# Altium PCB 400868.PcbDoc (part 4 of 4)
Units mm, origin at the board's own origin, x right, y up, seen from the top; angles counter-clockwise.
Board outline 117 x 63.5 mm, 4 copper layers (Top Layer, Mid-Layer 1, Mid-Layer 2, Bottom Layer), stack 1.58 mm thick; 211 components, 153 nets, 878 pads, 1351 vias.
Unrouted connection lines stored in the file: 16.
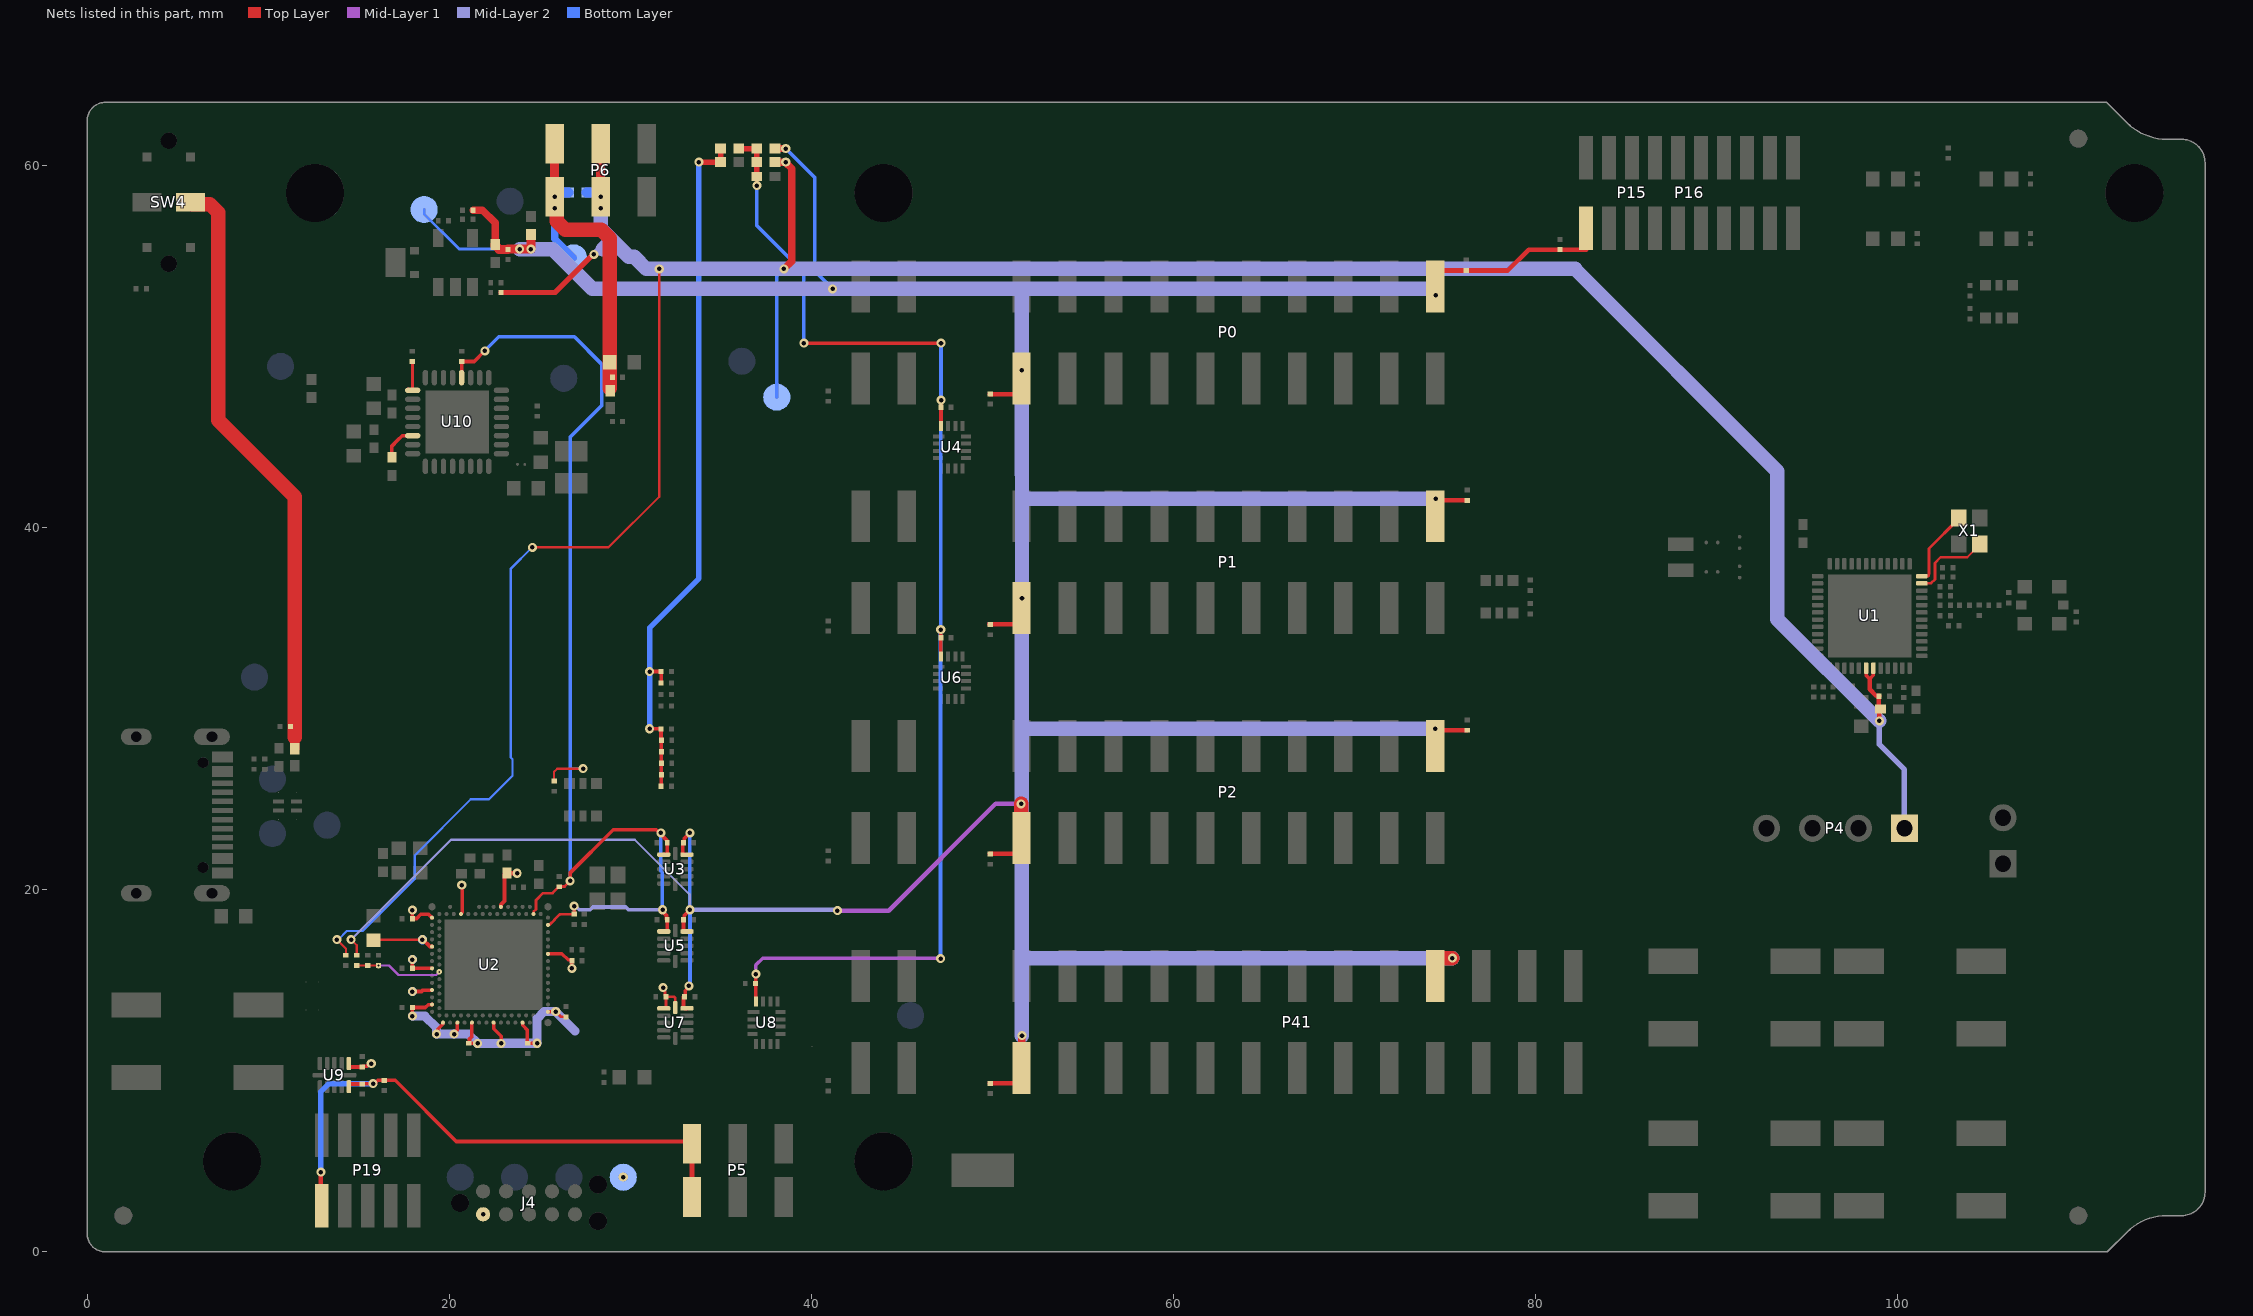
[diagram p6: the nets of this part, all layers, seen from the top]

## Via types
v1: diameter 0.5, hole 0.25, Top Layer to Bottom Layer, tented both sides, 1252 vias
v2: diameter 0.3, hole 0.1, Top Layer to Mid-Layer 1, tented top, 72 vias
v3: diameter 0.3, hole 0.1, Top Layer to Mid-Layer 1, tented both sides, 18 vias
v4: diameter 0.5, hole 0.25, Top Layer to Bottom Layer, tented bottom, 9 vias

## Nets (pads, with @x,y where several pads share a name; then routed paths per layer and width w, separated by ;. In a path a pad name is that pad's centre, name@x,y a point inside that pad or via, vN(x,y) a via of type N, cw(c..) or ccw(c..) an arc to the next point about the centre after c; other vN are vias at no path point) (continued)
VBUS:IN2: C46.2 FB3.2 SW4.5 | length 33.1
  Top Layer w0.5: FB3.2@11.475,27.8 11.475,28.423
  Top Layer w0.8: SW4.5@5.721,57.988 5.821,57.888 6.781,57.888 7.25,57.42 7.25,45.95 11.475,41.725 11.475,29.025 11.475,28.423
VBUS:OUT: C76.2 U10.22 | length 2
  Top Layer w0.2: C76.2@16.842,43.896 16.842,44.519 17.169,44.846 17.409,45.086 17.981,45.086 U10.22@17.992,45.096
VDD:DBGR: C15.2 C17.1 C18.1 C20.1 C22.1 C29.1 C31.1 C34.1 C35.1 C36.1 C37.1 C40.1 C53.2 C66.2 C68.2 J4.1 R6.2 R8.2 TP3.1 U2.A19 U2.AC1 U2.AG1 U2.AJ31 U2.AL3 U2.AL7 U2.AL11 U2.AL17 U2.AL25 U2.B8 U2.B28 U2.C1 U2.E31 U2.L1 U2.N31 U2.U1 U3.1 U5.1 U7.1 U7.12 U9.1 U10.12 | length 105.6
  Top Layer w0.125: C40.1@15.825,17.225 15.85,17.25 v1(18.525,17.25) ; R8.2@25.8,26.019 25.8,26.519 25.975,26.694 v1(27.4,26.694)
  Top Layer w0.15: U9.1@14.464,10.405 14.464,10.35 U9.1@14.514,10.3 ; U2.B28@24.66,18.664 24.675,18.679 24.675,18.801 24.798,18.925 24.798,19.204 24.798,19.428 25.185,19.815 25.722,19.815 26.081,20.174 C37.1@26.096,20.174 26.11,20.188 26.383,20.188 v1(26.685,20.49) ; U2.E31@25.443,18.079 25.562,18.079 25.824,18.341 25.824,18.364 26.102,18.642 26.125,18.642 26.134,18.651 26.899,18.651 C36.1@26.909,18.661 ; v1(25.893,13.271) 26.173,12.991 26.455,12.991 R6.2@26.46,12.986 ; v1(31.825,14.6) 31.825,14.505 31.929,14.402 31.929,14.16 31.946,14.143 C68.2@31.989,14.143 ; U7.1@31.86,13.45 31.939,13.45 31.989,13.5 C68.2@31.989,14.143 ; U7.12@32.5,13.5 32.5,14.012 32.412,14.1 32.031,14.1 C68.2@31.989,14.143
  Top Layer w0.187: U2.B8@20.66,18.664 20.66,18.675 20.735,18.75 v1@20.735,20.265 ; U2.N31@25.46,16.464 26.236,16.464 26.572,16.128 C35.1@26.692,16.128
  Top Layer w0.2: U9.1@14.489,10.625 14.464,10.6 U9.1@14.464,10.405 14.464,10.24 14.489,10.215 C53.2@15.2,10.215 15.235,10.25 15.469,10.25 15.619,10.4 v1(15.7,10.4) ; v1(17.968,13.03) 17.968,13.471 17.981,13.471 18.009,13.499 18.682,13.499 18.842,13.66 19.056,13.66 U2.AG1@19.06,13.664 ; v1(17.968,14.381) 17.976,14.388 18.482,14.388 18.558,14.464 U2.AC1@19.06,14.464 ; v1(17.968,18.884) 17.971,18.881 17.971,18.404 C17.1@17.974,18.401 17.992,18.42 18.209,18.42 18.439,18.65 18.865,18.65 19.046,18.469 19.049,18.469 19.056,18.462 19.056,18.46 U2.C1@19.06,18.464 ; C18.1@17.974,15.63 v1@17.974,16.149 ; C18.1@17.979,15.664 U2.U1@19.06,15.664 ; v1(18.525,17.25) 18.562,17.25 18.943,16.869 19.056,16.869 U2.L1@19.06,16.864 ; v1(19.314,12.026) 19.372,12.083 19.372,12.296 19.656,12.58 19.656,12.66 U2.AL3@19.66,12.664 ; v1(20.28,12.026) 20.28,12.107 20.46,12.288 U2.AL7@20.46,12.664 ; U10.12@20.7,48.304 20.7,49.19 21.39,49.19 v1(21.975,49.775) ; C22.1@21.092,11.524 21.127,11.559 21.13,11.559 21.13,11.759 21.26,11.889 U2.AL11@21.26,12.664 ; C22.1@21.101,11.521 21.572,11.521 v1(21.575,11.518) ; U2.AL17@22.46,12.664 22.46,12.334 22.878,11.916 v1(22.878,11.518) ; U2.AL25@24.06,12.664 24.065,12.66 24.065,12.514 24.318,12.261 24.318,11.549 C34.1@24.344,11.524 24.346,11.521 24.856,11.521 v1(24.86,11.525) ; U2.AJ31@25.46,13.264 25.887,13.264 v1(25.893,13.271) ; v1(26.685,20.49) 26.685,20.935 29.075,23.325 31.444,23.325 31.619,23.15 v1(31.7,23.15) 31.7,23.069 32.016,22.753 32.016,22.639 C15.2@32.051,22.604 32.051,21.975 32.026,21.95 U3.1@31.86,21.95 ; C35.1@26.692,16.128 26.748,16.128 26.783,16.093 C35.1@26.783,16.078 v1(26.782,15.659) ; v1@31.696,18.9 32.013,18.583 C66.2@32.013,18.389 ; U5.1@31.856,17.7 32.023,17.7 32.048,17.725 C66.2@32.048,18.354
  Top Layer w0.203: v1(26.908,19.101) 26.909,19.1 C36.1@26.909,18.661
  Top Layer w0.225: U2.A19@22.86,19.064 22.86,19.179 23.074,19.392 23.074,20.848 C31.1@23.15,20.924 ; C31.1@23.201,20.916 v1(23.759,20.916)
  Mid-Layer 1 w0.2: v1@21.541,11.484 v1(21.575,11.518) v1@21.632,11.461
  Mid-Layer 2 w0.2: v1(26.908,19.101) 26.989,19.101 27.19,18.9 27.803,18.9 27.953,19.05 29.761,19.05 29.911,18.9 v1(31.8,18.9)
  Mid-Layer 2 w0.5: v1(17.968,13.03) 18.666,13.03 19.295,12.401 19.295,12.045 v1(19.314,12.026) v1(20.28,12.026) 21.067,12.026 v1(21.575,11.518) v1(22.878,11.518) 22.885,11.525 v1(24.86,11.525) 24.86,12.889 25.242,13.271 v1(25.893,13.271) 26.964,12.2
  Bottom Layer w0.125: 26.685,26.694 v1(27.4,26.694)
  Bottom Layer w0.2: v1(21.575,11.518) v1@21.656,11.518 ; v1(21.878,2.074) v1@21.914,2.11 ; v1(21.975,49.775) 22.75,50.55 26.925,50.55 28.425,49.05 28.425,46.739 26.685,44.999 26.685,26.694 v1(26.685,20.49) ; v1(31.7,23.15) 31.7,21.046 31.775,20.971 31.775,18.925 v1(31.8,18.9)
  Bottom Layer w0.4: v1@17.968,18.911 v1(17.968,18.884) v1@17.987,18.865
  Bottom Layer w0.5: v1(17.968,14.381) v1@17.975,14.388 ; v1@18.534,17.242 v1(18.525,17.25) v1@18.534,17.258
  other v1: 29.621,4.125 17.975,16.15 20.7,20.266
VDD:IO: C16.1 C51.2 C52.2 C61.2 C62.2 C64.2 C65.2 C67.1 C69.1 C72.2 C79.2 C80.1 C81.2 P0.1 P0.20 P1.1 P1.20 P2.1 P2.20 P15.1 P16.1 P41.1 P41.20 R25.2 R46.2 R50.1 R54.2 TP11.1 U3.11 U5.11 U7.11 | length 271.4
  Top Layer w0.125: v1(14.589,17.251) 14.9,16.94 R46.2@14.9,16.385 ; U3.11@33.145,21.955 32.942,21.955 32.94,21.955 32.877,22.017 32.877,22.032 32.917,22.024 32.955,22.017 33.146,21.979 U3.11@33.149,21.979
  Top Layer w0.2: U3.11@32.942,21.955 32.917,21.98 32.917,22.024 32.917,22.558 32.918,22.574 32.988,22.644 32.988,22.838 v1(33.3,23.15) ; C69.1@32.952,14.104 32.952,13.475 32.977,13.45 U7.11@33.14,13.45 U7.11@33.144,13.45 ; C67.1@32.952,18.354 32.952,17.725 32.977,17.7 U5.11@33.14,17.7 U5.11@33.144,17.7 ; C69.1@32.987,14.135 33.05,14.135 33.05,14.419 33.25,14.619 v1(33.25,14.7) ; C67.1@32.987,18.389 32.987,18.583 v1@33.304,18.9
  Top Layer w0.25: U7.11@33.032,13.45 U7.11@33.14,13.45 ; C61.2@49.834,34.685 51.599,34.685 P1.1@51.599,35.56 ; C64.2@49.859,21.985 C64.2@49.9,21.985 51.624,21.985 P2.1@51.624,22.86 ; C51.2@49.859,47.385 51.624,47.385 P0.1@51.624,48.26 ; C79.2@49.871,9.314 P41.1@51.637,9.314 ; P0.20@74.484,53.34 74.484,54.215 C52.2@76.25,54.215 ; P2.20@74.485,28.815 C65.2@76.25,28.815 ; P1.20@74.485,41.515 C62.2@76.25,41.515 ; C52.2@76.2,54.215 78.49,54.215 79.64,55.365 C72.2@81.372,55.365 82.81,55.365 P15.1@82.81,56.375
  Top Layer w0.4: R25.2@21.32,57.55 21.85,57.55 22.55,56.85 C81.2@22.55,55.65 ; R50.1@38.105,60.95 v1(38.6,60.95) ; P41.1@51.624,10.16 51.637,10.173 51.637,11.937 v1(51.65,11.95)
  Top Layer w0.5: C81.2@22.55,55.65 22.55,55.6 22.765,55.385 C80.1@23.254,55.385 23.262,55.392 24.517,55.392 v1(24.525,55.4) R54.2@24.525,56.2
  Top Layer w0.8: v1(51.6,24.75) 51.6,22.884 P2.1@51.624,22.86 ; P41.20@74.484,15.24 74.484,16.117 74.592,16.225 v1(75.425,16.225)
  Mid-Layer 1 w0.25: v1(41.457,18.851) 44.288,18.851 50.187,24.75 v1(51.6,24.75)
  Mid-Layer 2 w0.125: v1(14.589,17.251) 20.113,22.775 30.251,22.775 33.3,19.726 v1(33.3,18.9)
  Mid-Layer 2 w0.25: v1(33.3,18.9) 41.407,18.9 v1(41.457,18.851)
  Mid-Layer 2 w0.4: v1(51.65,11.95) v1(51.65,11.95)
  Mid-Layer 2 w0.8: v1(23.9,55.4) v1(24.525,55.4) 25.7,55.4 27.9,53.2 v1(41.187,53.2) 51.629,53.2 ; 51.629,42.961 v1(51.629,48.712) 51.629,53.2 ; v1(51.65,11.95) v1@51.649,24.701 ; v1@51.649,24.799 51.649,28.905 ; v1(51.65,36.1) 51.649,28.905 ; v1(51.65,36.1) 51.65,41.595 51.65,42.941 ; 51.65,41.75 51.805,41.595 v1(74.504,41.595) ; 51.744,16.205 51.763,16.225 v1(75.425,16.225) ; v1(74.484,28.905) 51.649,28.905 ; v1(74.51,52.845) 74.155,53.2 51.629,53.2
  Bottom Layer w0.15: TP11.1@18.622,57.582 18.622,57.342 20.564,55.4 v1(23.9,55.4)
  Bottom Layer w0.2: v1(33.25,14.7) 33.307,14.757 33.307,15.201 33.313,15.206 33.313,18.887 v1(33.3,18.9) v1(33.3,23.15) ; v1(38.6,60.95) 40.2,59.35 40.2,54.187 v1(41.187,53.2)
VDD:SW: C19.1 C38.2 C70.1 C71.1 R50.2 R51.2 R52.2 U4.16 U6.16 U8.16 | length 69.7
  Top Layer w0.2: U8.16@36.945,13.825 v1(36.945,15.35) ; v1(37,58.9) 37,59.4 37.05,59.4 C38.2@37.025,59.375 ; v1(39.6,50.2) v1(47.175,50.2) ; U6.16@47.161,32.911 47.161,33.911 47.155,33.917 47.155,34.369 v1(47.161,34.375) ; U4.16@47.175,45.625 C19.1@47.175,46.615 ; C19.1@47.178,46.603 47.182,46.607 v1(47.182,47.056)
  Top Layer w0.3: R52.2@36,60.95 R50.2@37,60.95 R51.2@37,60.2 37,60.195 C38.2@37,59.4
  Mid-Layer 1 w0.2: v1(36.945,15.35) 36.945,15.845 37.325,16.225 47.125,16.225 v1(47.15,16.2)
  Bottom Layer w0.2: v1(37,58.9) 37,56.7 39.6,54.1 v1(39.6,50.2) ; v1(47.15,16.2) v1@47.15,34.364 ; v1(47.161,34.375) 47.164,34.379 v1@47.164,46.99 ; v1(47.175,50.2) 47.178,50.197 47.178,47.06 v1(47.182,47.056)
VDD:SW:PU: R13.1 R14.1 R15.1 R16.1 R17.1 R28.1 R29.1 R39.1 R52.1 R53.1 | length 39.6
  Top Layer w0.2: v1(31.075,28.9) 31.081,28.894 31.709,28.894 R14.1@31.715,28.888 31.708,28.88 R15.1@31.708,28.253 ; v1(31.075,32.053) 31.085,32.063 R28.1@31.715,32.063 R29.1@31.715,31.428 ; R39.1@31.708,25.713 31.723,25.728 31.723,26.335 31.708,26.35 31.731,26.373 31.731,26.964 31.708,26.987 31.731,27.01 31.731,27.601 31.708,27.624 31.731,27.647 31.731,28.244 R15.1@31.708,28.267
  Top Layer w0.3: v1(33.8,60.2) R53.1@35,60.2 R52.1@35,60.95
  Bottom Layer w0.3: v1(31.075,28.9) 31.075,34.475 33.8,37.2 v1(33.8,60.2)
VDD:SWD0: C21.1 P5.3 P19.1 R18.2 U9.11 | length 33
  Top Layer w0.2: U9.11@14.464,9.125 14.464,9.252 14.489,9.277 15.2,9.277 15.216,9.292 15.792,9.292 v1(15.8,9.3) 15.88,9.3 16.056,9.475 R18.2@16.409,9.475 17.025,9.475 20.4,6.1 33.285,6.1 P5.3@33.42,5.965
  Top Layer w0.25: v1(12.913,4.411) 12.913,2.782 12.823,2.692 P19.1@12.964,2.55 ; P5.3@33.42,3.035 P5.3@33.42,5.965
  Bottom Layer w0.3: v1(12.913,4.411) 12.913,8.854 13.358,9.3 v1(15.8,9.3)
VDDL: C25.2 C58.1 FB4.2 P6.3 R2.2 TP9.1 | length 21
  Top Layer w0.5: P6.3@25.835,58.929 P6.3@25.835,61.219
  Top Layer w0.8: P6.3@25.835,58.52 v1(25.835,58.289) 25.835,57.88 v1(25.835,57.648) 25.891,57.648 25.945,57.594 25.945,56.944 26.414,56.475 28.406,56.475 28.875,56.006 C58.1@28.875,49.139 28.875,48.321 FB4.2@28.875,47.7
  Bottom Layer w0.4: 25.832,59.141 25.832,55.96 TP9.1@26.878,54.915
  Bottom Layer w0.55: v1@25.835,58.52 R2.2@26.602,58.52
VDDL:nRF: C1.2 C2.2 P4.1 P6.2 R2.1 R23.2 R48.1 R51.1 TP1.1 U1.18 U1.19 | length 172.5
  Top Layer w0.125: v1(13.8,17.251) 14.3,16.751 R23.2@14.3,16.385 ; v1(24.6,38.925) 28.813,38.925 31.61,41.722 v1(31.61,54.3)
  Top Layer w0.2: U1.18@98.28,32.105 98.28,31.852 98.48,31.652 98.68,31.852 U1.19@98.68,32.105
  Top Layer w0.25: 98.48,31.652 98.48,31.078 98.829,30.73 98.985,30.73 98.995,30.72 98.995,30.69 98.98,30.675 C1.2@98.98,30.077 ; v1@99.008,29.33 C1.2@99.008,30.062 ; v1@99.01,29.262 v1(99.01,29.33)
  Top Layer w0.3: R48.1@22.87,53 25.858,53 27.958,55.1 v1(28,55.1)
  Top Layer w0.4: R51.1@38.105,60.2 v1(38.6,60.2) 38.6,60.173 38.925,59.848 38.925,54.725 v1(38.5,54.3)
  Top Layer w0.5: v1(28.375,58.289) P6.2@28.375,61.219
  Mid-Layer 2 w0.3: v1(99.01,29.33) 99.01,28.032 100.4,26.641 P4.1@100.4,23.4
  Mid-Layer 2 w0.4: v1(28,55.1) 28.027,55.1 28.31,55.383 28.479,55.383
  Mid-Layer 2 w0.8: 28.372,56.524 29.921,54.975 30.221,54.975 30.896,54.3 v1(31.61,54.3) v1(38.5,54.3) 82.2,54.3 93.382,43.118 93.382,34.957 v1(99.01,29.33) ; 28.372,56.604 28.372,58.517 v1@28.375,58.52 ; 28.479,55.383 28.675,55.579
  Bottom Layer w0.125: v1@13.84,17.25 13.875,17.25 14.35,17.725 15.225,17.725 18.1,20.6 18.1,21.9 21.2,25 22.2,25 23.5,26.3 23.5,27.219 23.4,27.319 23.4,37.725 v1(24.6,38.925)
  Bottom Layer w0.2: TP1.1@38.104,47.219 38.104,53.904 v1(38.5,54.3)
  Bottom Layer w0.55: R2.1@27.602,58.52 v1@28.375,58.52
  other v1: 28.375,57.648
VMEAS_CH1: C87.1 R46.1 R47.2 U2.V2 | length 4.8
  Top Layer w0.125: R46.1@14.9,15.815 v2(16.1,15.815)
  Mid-Layer 1 w0.125: v2(16.1,15.815) 16.685,15.815 17.2,15.3 19.296,15.3 v3(19.46,15.464)
VSET1: R26.1 U10.17 | length 1.9
  Top Layer w0.15: U10.17@17.742,47.665 17.811,47.596 U10.17@17.992,47.596 17.974,47.614 R26.1@17.974,49.183
XC1: U1.35 X1.1 | length 4.5
  Top Layer w0.125: 102.081,38.062 102.394,38.375 103.874,38.375 104.55,39.05 X1.1@104.55,39.1
  Top Layer w0.15: U1.35@101.507,36.932 101.517,36.941 101.873,36.941 102.081,37.149 102.081,38.062
XC2: U1.36 X1.3 | length 4.1
  Top Layer w0.15: U1.36@101.507,37.332 101.719,37.332 101.742,37.355 101.742,37.427 101.759,37.445 101.759,38.859 103.4,40.5 X1.3@103.4,40.55
pads on no net: Fid1.0 Fid2.0 Fid3.0 J3. J3.0 J3.A8 J3.B8 J4.0 J4.6 J4.7 J4.8 J4.9 P0.8 P0.9 P0.10 P0.11 P0.12 P0.13 P0.14 P0.15 P0.16 P0.17 P0.18 P2.13 P2.14 P2.15 P2.16 P2.17 P2.18 P5.2 P15.7 P15.8 P16.7 P16.8 P16.11 P16.13 P19.7 P19.8 P19.9 P30.3 P31.3 P32.3 P40.3 SW4.0 SW4.1 SW4.6 U2. U2.A1 U2.A21 U2.A31 U2.AD2 U2.AE31 U2.AG31 U2.AH2 U2.AK2 U2.AK4 U2.AK6 U2.AK8 U2.AK10 U2.AK12 U2.AK14 U2.AK22 U2.AK24 U2.AK26 U2.AK28 U2.AK30 U2.AL1 U2.AL31 U2.B10 U2.B14 U2.D2 U2.F2 U2.J1 U2.K2 U2.M2 U2.P2 U2.T2 U2.Y2 U4.7 U4.12 U6.7 U6.12 U8.7 U8.12 U10.5 U10.7 U10.9 U10.10 U10.11 U10.15 U10.18 U10.19 U10.25 U10.26 U10.27 U11.4

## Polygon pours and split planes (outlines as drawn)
GND on Top Layer "Top_Layer-GND" (solid, remove dead copper, pour order 6): 0.002,0.009 0.002,63.509 117.004,63.509 117.004,0.009
5V0 on Top Layer "Top_Layer-5V0" (solid, remove dead copper, pour order 0): 15.125,47.746 15.125,48.639 17.748,51.263 17.748,59.646 17.294,60.1 14.15,60.1 10.475,56.425 10.475,48.223 10.952,47.746
GND on Top Layer "GND_island" (solid, pour order 4): 103.874,35.423 103.874,34.914 104.306,34.482 104.991,34.482 105.397,34.888 105.397,35.422
GND on Mid-Layer 2 "Mid_Layer2-GND" (solid, remove dead copper, pour order 7): 0.029,0 0.029,63.5 117.004,63.5 117.004,0
VDD:DBGR on Mid-Layer 2 "VDD_DBGR" (solid, pour order 5): 21.754,1.825 25.2,1.825 26.025,2.65 29.177,2.65 30.011,3.485 30.011,4.789 28.85,5.95 28.85,11 32.25,14.4 32.25,18.875 29.675,21.45 19,21.45 17.725,20.175 17.725,14.809 15.175,12.259 15.175,10.025 15.325,9.875 21.219,3.981 21.219,2.36
5V0 on Mid-Layer 2 "5V0_PWR" (solid, pour order 2): 24.26,44.165 25.342,45.246 25.342,45.946 24.26,47.028 24.26,48.92 24.225,48.95 13.642,48.95 13.642,45.946 15.492,45.946 19.438,42 24.136,42 24.26,42.125
GND on Mid-Layer 1 "Mid_Layer1-GND" (solid, remove dead copper, pour order 1): 0.029,0 0.029,63.22 117.004,63.22 117.004,0
GND on Bottom Layer "Bottom_Layer-GND" (solid, remove dead copper, pour order 3): 0.029,0 0.029,63.5 117.004,63.5 117.004,0

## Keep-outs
Top Layer:
  region: 44.004,55.5 cw(c44.004,58.5) 41.004,58.5 cw(c44.004,58.5) 44.004,61.5 cw(c44.004,58.5) 47.004,58.5 cw(c44.004,58.5)
  region: 113.104,55.5 cw(c113.104,58.5) 110.104,58.5 cw(c113.104,58.5) 113.104,61.5 cw(c113.104,58.5) 116.104,58.5 cw(c113.104,58.5)
  region: 106.005,1.979 cw(c106.005,4.979) 103.005,4.979 cw(c106.005,4.979) 106.005,7.979 cw(c106.005,4.979) 109.005,4.979 cw(c106.005,4.979)
  region: 44.004,2 cw(c44.004,5) 41.004,5 cw(c44.004,5) 44.004,8 cw(c44.004,5) 47.004,5 cw(c44.004,5)
  region: 8.004,2 cw(c8.004,5) 5.004,5 cw(c8.004,5) 8.004,8 cw(c8.004,5) 11.004,5 cw(c8.004,5)
  region: 77.796,54.973 cw(c77.796,58.473) 74.296,58.473 cw(c77.796,58.473) 77.796,61.973 cw(c77.796,58.473) 81.296,58.473 cw(c77.796,58.473)
  region: 35.496,52.473 cw(c35.496,55.973) 31.996,55.973 cw(c35.496,55.973) 35.496,59.473 cw(c35.496,55.973) 38.996,55.973 cw(c35.496,55.973)
  region: 16.496,56.973 cw(c16.496,60.473) 12.996,60.473 cw(c16.496,60.473) 16.496,63.973 cw(c16.496,60.473) 19.996,60.473 cw(c16.496,60.473)
  region: 20.496,33.473 cw(c20.496,36.973) 16.996,36.973 cw(c20.496,36.973) 20.496,40.473 cw(c20.496,36.973) 23.996,36.973 cw(c20.496,36.973)
  region: 3.496,-0.027 cw(c3.496,3.473) -0.004,3.473 cw(c3.496,3.473) 3.496,6.973 cw(c3.496,3.473) 6.996,3.473 cw(c3.496,3.473)
  region: 74.996,0.473 cw(c74.996,3.973) 71.496,3.973 cw(c74.996,3.973) 74.996,7.473 cw(c74.996,3.973) 78.496,3.973 cw(c74.996,3.973)
  region: 42.496,14.473 cw(c42.496,17.973) 38.996,17.973 cw(c42.496,17.973) 42.496,21.473 cw(c42.496,17.973) 45.996,17.973 cw(c42.496,17.973)
  region: 108.496,6.473 cw(c108.496,9.973) 104.996,9.973 cw(c108.496,9.973) 108.496,13.473 cw(c108.496,9.973) 111.996,9.973 cw(c108.496,9.973)
  region: 112,26.473 cw(c112,29.973) 108.5,29.973 cw(c112,29.973) 112,33.473 cw(c112,29.973) 115.5,29.973 cw(c112,29.973)
  region: 16.439,59.569 cw(c16.439,62.569) 13.439,62.569 cw(c16.439,62.569) 16.439,65.569 cw(c16.439,62.569) 19.439,62.569 cw(c16.439,62.569)
  region: 98.967,25.576 cw(c98.967,28.576) 95.967,28.576 cw(c98.967,28.576) 98.967,31.576 cw(c98.967,28.576) 101.967,28.576 cw(c98.967,28.576)
  region: 46.352,19.687 ccw(c49.352,19.687) 49.352,16.687 ccw(c49.352,19.687) 52.352,19.687 ccw(c49.352,19.687) 49.352,22.687 ccw(c49.352,19.687)
Keep-Out Layer:
  circle w0.152: c12.604,58.5 r2.4
  circle w0.152: c113.104,58.5 r2.4
  circle w0.152: c113.104,58.5 r2.4
  circle w0.152: c44.004,5 r2.4
  circle w0.152: c44.004,58.5 r2.4
  circle w0.152: c8.004,5 r2.4

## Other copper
Top Layer:
  rectangle net GND: 6.919,27.025 8.804,27.85
  rectangle net GND: 109.224,34.036 110.038,34.931
  rectangle net GND: 6.891,20.422 8.776,21.247
  rectangle net PCBANT: 115.025,17.475 116.295,18.175
  pour cut-out: 105.311,41.332 105.311,38.077 102.443,38.077 102.443,41.332
  pour cut-out: 32.2,13.4 32.8,13.4 32.8,11.85 32.2,11.85
  pour cut-out: 32.2,21.9 32.8,21.9 32.8,20.35 32.2,20.35
  region net RF: 106.555,35.98 106.35,35.865 106.35,35.595 106.555,35.48
  pour cut-out: 97.313,29.648 97.313,29.952 97.2,29.952 97.2,29.648
  pour cut-out: 12.914,9.465 12.914,10.065 14.464,10.065 14.464,9.465
  pour cut-out: 32.2,17.65 32.8,17.65 32.8,16.1 32.2,16.1
  pour cut-out: 19.46,18.664 25.46,18.664 25.46,13.064 19.46,13.064
  pour cut-out: 18.4,47.9 22.5,47.9 22.5,43.8 18.4,43.8
  pour cut-out: 95.65,37.9 101.2,37.9 101.2,32.3 95.65,32.3
  region net NetC27_2: 24.549,42.586 25.69,42.586 25.817,42.713 25.817,43.016 27.652,43.016 27.652,41.589 27.474,41.411 24.549,41.411
  region net 5V0: 23.604,45.459 24.467,44.596 25.267,44.596 25.267,46.296 24.167,46.296 23.604,45.733
  region net PVSS1: 22.892,44.446 23.264,44.446 23.499,44.211 23.499,43.936 23.199,43.636 23.199,41.786 23.949,41.786 23.949,42.536 24.65,43.237 25.267,43.237 25.267,43.996 24.164,43.996 23.414,44.746 22.892,44.746
  pour cut-out: 8.2,23.75 10.573,23.75 10.573,24.279 8.2,24.279 8.2,24.047
  pour cut-out: 103.765,35.421 103.765,34.912 104.197,34.48 104.883,34.48 105.289,34.887 105.289,34.888 105.289,35.421 105.439,35.421 105.439,34.801 104.957,34.318 104.118,34.318 103.61,34.826 103.61,35.421
  pour cut-out: 102.668,36.897 102.668,36.593 102.78,36.593 102.78,36.897
  region net 5V0: 17.992,46.246 17.547,46.246 17.022,46.771 16.564,46.771 16.089,47.246 15.042,47.246 15.042,48.846 13.642,48.846 13.642,45.946 17.992,45.946
  region net VBUS: 17.967,45.446 17.392,45.446 17.067,45.121 15.492,45.121 15.092,44.721 13.142,44.721 13.142,45.746 17.967,45.746
  pour cut-out: 25.83,43.7 25.83,42.98 27.85,42.98 27.85,43.7
  region net NetC59_1: 7.89,19.8 7.89,18.1 5.902,18.1 5.902,19.8
  region net VBUS:IN: 11.725,27.175 11.725,26.525 10.879,26.525 10.879,25.283 10.101,25.283 9.725,25.659 9.725,26.15 9.641,26.234 6.876,26.234 6.719,26.077 6.719,22.178 6.864,22.034 8.059,22.034 8.059,21.434 6.873,21.434 5.95,22.357 5.95,25.875 6.909,26.834 9.937,26.834 10.232,26.539 10.232,25.828 10.577,25.483 10.679,25.483 10.679,25.554 10.35,25.883 10.35,27.175
  region net ANT: 102.262,35.879 101.873,35.829 101.873,35.63 102.262,35.579
Mid-Layer 1:
  pour cut-out: 110.038,37.125 106.927,37.125 106.302,36.5 102.775,36.5 102.775,35.324 103.7,35.324 103.7,34.95 106.302,34.95 106.927,34.325 110.038,34.325
  pour cut-out: 103.61,35.317 103.61,34.827 104.118,34.319 104.957,34.319 105.439,34.801 105.439,35.317
  pour cut-out: 89.123,38.461 89.123,39.916 90.485,39.916 90.485,38.461
  pour cut-out: 89.123,36.835 89.123,38.291 90.485,38.291 90.485,36.835
  pour cut-out: 12.225,12.775 12.225,13.975 12.717,13.975 12.717,12.775
Mid-Layer 2:
  pour cut-out: 110.038,37.125 106.927,37.125 106.302,36.5 102.775,36.5 102.775,35.324 103.7,35.324 103.7,34.95 106.302,34.95 106.927,34.325 110.038,34.325
  pour cut-out: 103.61,35.317 103.61,34.827 104.118,34.319 104.957,34.319 105.439,34.801 105.439,35.317
Bottom Layer:
  rectangle net 5V0: 13.4,45.85 15.2,49.075
  pour cut-out: 19.58,57.582 cw(c18.628,57.582) 18.628,56.63 cw(c18.628,57.578) 17.68,57.578 17.68,57.589 cw(c18.621,57.589) 18.621,58.53 18.632,58.53 cw(c18.632,57.582)
  pour cut-out: 16.398,44.858 cw(c15.446,44.858) 15.446,43.906 cw(c15.446,44.854) 14.498,44.854 14.498,44.865 cw(c15.439,44.865) 15.439,45.806 15.449,45.806 cw(c15.449,44.858)
  pour cut-out: 20.072,29.999 cw(c19.12,29.999) 19.12,29.047 cw(c19.12,29.995) 18.172,29.995 18.172,30.006 cw(c19.113,30.006) 19.113,30.947 19.124,30.947 cw(c19.124,29.999)
  pour cut-out: 10.085,12.152 cw(c9.134,12.152) 9.134,11.2 cw(c9.134,12.149) 8.185,12.149 8.185,12.159 cw(c9.127,12.159) 9.127,13.1 9.137,13.1 cw(c9.137,12.152)
  pour cut-out: 23.027,54.815 cw(c22.075,54.815) 22.075,53.863 cw(c22.075,54.811) 21.127,54.811 21.127,54.822 cw(c22.068,54.822) 22.068,55.763 22.079,55.763 cw(c22.079,54.815)
  pour cut-out: 15.483,54.307 cw(c14.531,54.307) 14.531,53.355 cw(c14.531,54.303) 13.583,54.303 13.583,54.314 cw(c14.524,54.314) 14.524,55.255 14.535,55.255 cw(c14.535,54.307)
  pour cut-out: 32.984,37.568 cw(c32.032,37.568) 32.032,36.617 cw(c32.032,37.565) 31.084,37.565 31.084,37.576 cw(c32.025,37.576) 32.025,38.517 32.036,38.517 cw(c32.036,37.568)
  pour cut-out: 38.369,38.713 cw(c37.417,38.713) 37.417,37.762 cw(c37.417,38.71) 36.469,38.71 36.469,38.72 cw(c37.41,38.72) 37.41,39.662 37.42,39.662 cw(c37.42,38.713)
  pour cut-out: 39.869,42.397 cw(c38.918,42.397) 38.918,41.445 cw(c38.918,42.393) 37.97,42.393 37.97,42.404 cw(c38.911,42.404) 38.911,43.345 38.921,43.345 cw(c38.921,42.397)
  pour cut-out: 27.284,48.262 cw(c26.332,48.262) 26.332,47.31 cw(c26.332,48.258) 25.384,48.258 25.384,48.269 cw(c26.325,48.269) 26.325,49.21 26.336,49.21 cw(c26.336,48.262)
  pour cut-out: 14.213,38.847 cw(c13.261,38.847) 13.261,37.895 cw(c13.261,38.843) 12.313,38.843 12.313,38.854 cw(c13.254,38.854) 13.254,39.795 13.265,39.795 cw(c13.265,38.847)
  pour cut-out: 11.191,41.354 cw(c10.239,41.354) 10.239,40.403 cw(c10.239,41.351) 9.291,41.351 9.291,41.362 cw(c10.232,41.362) 10.232,42.303 10.242,42.303 cw(c10.242,41.354)
  pour cut-out: 11.191,38.354 cw(c10.239,38.354) 10.239,37.403 cw(c10.239,38.351) 9.291,38.351 9.291,38.362 cw(c10.232,38.362) 10.232,39.303 10.242,39.303 cw(c10.242,38.354)
  pour cut-out: 16.982,27.612 cw(c16.03,27.612) 16.03,26.66 cw(c16.03,27.608) 15.082,27.608 15.082,27.619 cw(c16.023,27.619) 16.023,28.56 16.034,28.56 cw(c16.034,27.612)
  pour cut-out: 22.748,27.434 cw(c21.796,27.434) 21.796,26.482 cw(c21.796,27.43) 20.848,27.43 20.848,27.441 cw(c21.789,27.441) 21.789,28.382 21.799,28.382 cw(c21.799,27.434)
  pour cut-out: 25.748,28.424 cw(c24.796,28.424) 24.796,27.473 cw(c24.796,28.421) 23.848,28.421 23.848,28.432 cw(c24.789,28.432) 24.789,29.373 24.799,29.373 cw(c24.799,28.424)
  pour cut-out: 28.748,28.424 cw(c27.796,28.424) 27.796,27.473 cw(c27.796,28.421) 26.848,28.421 26.848,28.432 cw(c27.789,28.432) 27.789,29.373 27.799,29.373 cw(c27.799,28.424)
  pour cut-out: 38.165,26.748 cw(c37.213,26.748) 37.213,25.796 cw(c37.213,26.744) 36.265,26.744 36.265,26.755 cw(c37.206,26.755) 37.206,27.696 37.217,27.696 cw(c37.217,26.748)
  pour cut-out: 38.165,21.748 cw(c37.213,21.748) 37.213,20.796 cw(c37.213,21.744) 36.265,21.744 36.265,21.755 cw(c37.206,21.755) 37.206,22.696 37.217,22.696 cw(c37.217,21.748)
  pour cut-out: 38.165,16.748 cw(c37.213,16.748) 37.213,15.796 cw(c37.213,16.744) 36.265,16.744 36.265,16.755 cw(c37.206,16.755) 37.206,17.696 37.217,17.696 cw(c37.217,16.748)
  pour cut-out: 38.165,11.748 cw(c37.213,11.748) 37.213,10.796 cw(c37.213,11.744) 36.265,11.744 36.265,11.755 cw(c37.206,11.755) 37.206,12.696 37.217,12.696 cw(c37.217,11.748)
Multi-Layer:
  pour cut-out: 110.035,0.028 117.023,0.028 116.971,63.5 110.041,63.5

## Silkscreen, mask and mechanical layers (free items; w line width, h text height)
Top Overlay:
  circle w0.15: c27.103,56.235 r0.884
  circle w0.15: c92.78,23.4 r1.13
  circle w0.381: c12.3,0.8 r0.127
  region: 91.422,22.18 91.422,23.404 cw(c92.792,23.404) 92.807,24.775 92.807,24.505 ccw(c92.797,23.45) 91.742,23.45 91.742,23.299 ccw(c92.797,23.299) 92.797,22.245 92.797,22.18
  region: 94.176,22.18 94.176,23.405 ccw(c92.806,23.404) 92.801,24.775 92.801,24.505 cw(c92.801,23.45) 93.856,23.45 93.856,23.3 cw(c92.801,23.3) 92.801,22.245 92.801,22.181
  region: 24.978,54.351 25.678,55.243 26.353,54.351
  region: 29.216,55.223 28.516,54.331 27.841,55.223
  region: 113.007,18.121 113.87,17.475 113.007,16.836
  lines w0.127: 113.674,15.975 114.674,15.975 ; 113.674,16.975 114.674,16.975 ; 113.674,17.975 114.674,17.975 ; 113.674,18.975 114.674,18.975 ; 114.174,16.475 114.674,16.475 ; 114.174,17.475 114.674,17.475 ; 114.174,18.475 114.674,18.475
  lines w0.15: 14.142,43.575 14.142,40.767 29.075,40.767 29.075,45.225 29.075,45.599 ; 14.142,47.346 14.142,50.261 29.071,50.261 ; 15.879,15.494 15.879,11.244 20.675,11.244 ; 15.879,19.075 15.879,26.525 29.075,26.525 29.078,21.575 ; 21.539,11.244 23.851,11.244 ; 24.841,11.244 29.078,11.244 ; 29.075,11.244 29.075,18.575 ; 29.075,49.664 29.075,50.261 ; 30.153,55.498 31.653,55.498 ; 30.453,55.248 31.353,55.248 ; 30.703,55.003 31.103,55.003 ; 30.903,55.498 30.903,56.248 ; 42.204,29.8 42.204,30.3 42.45,30.3 ; 42.204,42.5 42.204,43 42.45,43 ; 42.204,55.2 42.204,55.7 42.45,55.7 ; 45.534,43.011 45.779,43.011 45.779,42.511 ; 45.559,30.3 45.804,30.3 45.804,29.8 ; 45.559,55.7 45.804,55.7 45.804,55.2 ; 94,40.675 94,28.175 105.875,28.175 105.875,35.1 ; 102.85,42.325 105.875,42.325 105.875,37.363
  lines w0.178: 25.671,55.468 25.671,55.648 ; 25.671,55.933 25.671,56.246 25.928,56.246 ; 28.278,56.248 28.528,56.248 28.528,55.935 ; 28.528,55.456 28.528,55.637
  text "ON" at 0.35,61.3 h1.4
  text "LED0" at 97.318,59.925 h1.8
  text "LED1" at 103.58,59.925 h1.8
  text "GPIO pins shown in parentheses are only available on headers with modification" at 50.325,59.25 h1.6
  text "VDDL / CURRENT / MEASURE" at 16.649,58.208 h1.8
  text "LED2" at 97.318,56.625 h1.8
  text "LED3" at 103.58,56.625 h1.8
  text "A" at 26.653,55.798 h1.52
  text "VDD / IO" at 72.536,55.32 h1.52
  text "GND" at 50.025,55.229 h1.52
  text "01" at 53.487,55.229 h1.52
  text "03" at 55.921,55.229 h1.52
  text "GND" at 42.605,55.215 h1.52
  text "POWER" at 8.575,54.488 h1.8 r90
  text "OFF" at 0.35,53.425 h1.4
  text "IDD" at 26.128,52.048 h1.52 r90
  text "GND" at 31.378,51.273 h1.52 r90
  text "DEBUG IN/ TRACE" at 84.325,50.8 h1.8
  text "nRF54" at 28.928,50.548 h1.52 r90
  text "PMIC" at 14.075,50.275 h1.8
  text "PORT0" at 49.675,46.672 h1.8 r90
  text "5V0" at 41.12,45.229 h1.52
  text "00" at 53.381,45.229 h1.52
  text "02" at 55.921,45.229 h1.52
  text "04" at 58.461,45.229 h1.52
  text "GND" at 73.289,45.229 h1.52
  text "VDD / IO" at 49.276,44.22 h1.52
  text "VDD / IO" at 72.536,42.62 h1.52
  text "GND" at 50.025,42.529 h1.52
  text "05" at 58.461,42.529 h1.52
  text "07" at 61.001,42.529 h1.52
  text "09" at 63.541,42.529 h1.52
  text "11" at 66.24,42.529 h1.52
  text "13" at 68.78,42.529 h1.52
  text "15" at 71.32,42.529 h1.52
  text "GND" at 42.605,42.515 h1.52
  text "(01)" at 53.205,42.449 h1.52
  text "(03)" at 55.612,42.449 h1.52
  text "nRF54LV10A" at 93.931,40.7 h1.8
  text ".PCBNumber" at 0.598,38.543 h2.03
  text ".PCBRevision" at 0.598,37.381 h1.52
  text "PORT1" at 49.675,33.972 h1.8 r90
  text ".ProductName" at 0.515,33.45 h3
  text "5V0" at 41.12,32.529 h1.52
  text "04" at 58.461,32.529 h1.52
  text "06" at 61.001,32.529 h1.52
  text "08" at 63.541,32.529 h1.52
  text "10" at 66.134,32.529 h1.52
  text "12" at 68.674,32.529 h1.52
  text "14" at 71.214,32.529 h1.52
  text "GND" at 73.289,32.529 h1.52
  text "(00)" at 53.031,32.449 h1.52
  text "(02)" at 55.518,32.449 h1.52
  text "VDD / IO" at 49.276,31.52 h1.52
  text "VDD / IO" at 72.536,29.92 h1.52
  text "GND" at 50.025,29.829 h1.52
  text "17" at 53.487,29.829 h1.52
  text "19" at 55.921,29.829 h1.52
  text "21" at 58.206,29.829 h1.52
  text "23" at 61.001,29.829 h1.52
  text "25" at 63.541,29.829 h1.52
  text "GND" at 42.605,29.815 h1.52
  text "DEBUGGER" at 0.587,29.149 h1.8
  text "DEBUGGER" at 15.813,26.525 h1.8
  text "GND" at 106.825,23.35 h1.4
  text "PORT1" at 49.675,21.272 h1.8 r90
  text "DECB" at 96.6,21 h1.27
  text "GND" at 91.425,20.95 h1.4
  text "nRF54 / NRESET" at 106.9,20.7 h1.27
  text "DECD" at 94.2,19.9 h1.27
  text "VDDL:nRF" at 98.2,19.9 h1.27
  text "5V0" at 41.12,19.829 h1.52
  text "16" at 53.381,19.829 h1.52
  text "18" at 55.921,19.829 h1.52
  text "20" at 58.461,19.829 h1.52
  text "22" at 61.001,19.829 h1.52
  text "24" at 63.541,19.829 h1.52
  text "GND" at 73.289,19.829 h1.52
  text "VDD / IO" at 49.276,18.82 h1.52
  text "BUTTON 0" at 87,17.287 h1.8
  text "BUTTON 1" at 97.262,17.287 h1.8
  text "B0" at 53.437,16.922 h1.52
  text "D1" at 61.119,16.928 h1.52
  text "E1" at 63.621,16.928 h1.52
  text "F1" at 68.862,16.928 h1.52
  text "GND" at 50.225,16.909 h1.52
  text "C1" at 56.004,16.912 h1.52
  text "C3" at 58.493,16.912 h1.52
  text "D3" at 66.132,16.912 h1.52
  text "G0" at 71.096,16.902 h1.52
  text "VDD / IO" at 72.334,16.908 h1.52
  text "H1" at 76.447,16.898 h1.52
  text "H3" at 78.808,16.901 h1.52
  text "H5" at 81.34,16.892 h1.52
  text "RESET" at 2.096,14.865 h1.8
  text "EXPAN" at 49.675,8.625 h1.8 r90
  text "BUTTON 2" at 87,7.786 h1.8
  text "BUTTON 3" at 97.262,7.786 h1.8
  text "GND" at 38.975,7.7 h1.52 r90
  text "D2" at 66.145,7.547 h1.52
  text "F0" at 68.196,7.55 h1.52
  text "C4" at 71.17,7.55 h1.52
  text "H4" at 81.326,7.546 h1.52
  text "A0" at 53.346,7.54 h1.52
  text "C0" at 55.917,7.531 h1.52
  text "C2" at 58.506,7.531 h1.52
  text "D0" at 61.016,7.54 h1.52
  text "E0" at 63.616,7.54 h1.52
  text "GND" at 73.089,7.534 h1.52
  text "H0" at 76.232,7.52 h1.52
  text "H2" at 78.821,7.536 h1.52
  text "VDD / SWD0" at 35,7.206 h1.52 r90
  text "VDD / IO" at 49.631,6.429 h1.52
  text "GND" at 47.315,2.03 h1.4
  text "DEBUG OUT" at 3.35,1.325 h1.8
  text "3.6V Max" at 13.05,0.325 h1.4
Bottom Overlay:
  drawing of 290 lines, arcs and shapes, not listed
  text "P1.11" at 24.36,41.699 h1.91 r180
  text "SWO" at 31.069,41.699 h1.91 r180
  text "nRF54" at 38.559,41.538 h2.03 r180
  text "SWDCLK" at 29.523,39.224 h1.91 r180
  text "SWDIO" at 30.27,36.674 h1.91 r180
  text "DEBUGGER" at 39.111,35.472 h1.4 r180
  text "RESET" at 30.926,34.074 h1.91 r180
  text "BUTTON 3" at 84.273,33.228 h1.91 r180
  text "P0.04" at 79.108,32.609 h1.91 r180
  text "CTS1" at 31.278,31.624 h1.91 r180
  text "P1.07" at 23.819,31.619 h1.91 r180
  text "BUTTON 2" at 84.298,30.558 h1.91 r180
  text "P1.08" at 79.108,29.909 h1.91 r180
  text "RTS1" at 31.371,29.084 h1.91 r180
  text "P1.06" at 23.819,29.079 h1.91 r180
  text "nRF54" at 38.606,28.511 h2.03 r180
  text "BUTTON 1" at 84.298,27.854 h1.91 r180
  text "P1.09" at 79.104,27.232 h1.91 r180
  text "P1.04" at 23.819,26.539 h1.91 r180
  text "TXD1" at 31.136,26.54 h1.91 r180
  text "GPIO" at 92.825,25.733 h1.78 r180
  text "BUTTON 0" at 84.265,25.202 h1.91 r180
  text "PIN" at 38.458,24.51 h1.78 r180
  text "P1.21" at 79.108,24.509 h1.91 r180
  text "P1.05" at 23.819,23.999 h1.91 r180
  text "RXD1" at 31.124,24 h1.91 r180
  text "SB6" at 63.141,21.847 h1.91 r180
  text "P1.22" at 79.104,21.847 h1.91 r180
  text "LED 3" at 85.835,21.834 h1.91 r180
  text "CTS0" at 31.01,21.465 h1.91 r180
  text "P0.03" at 23.819,21.46 h1.91 r180
  text "P1.14" at 49.171,20.461 h1.91 r180
  text "XL2" at 56.689,20.439 h1.91 r180
  text "1M" at 93.863,20.269 h1.52 r180
  text "GPIO" at 69.872,19.424 h1.78 r180
  text "SB4" at 63.141,19.155 h1.91 r180
  text "P1.25" at 79.104,19.154 h1.91 r180
  text "LED 2" at 85.835,19.155 h1.91 r180
  text "RTS0" at 31.103,18.925 h1.91 r180
  text "P0.02" at 23.819,18.92 h1.91 r180
  text "GPIO" at 92.834,17.621 h1.78 r180
  text "DEBUGGER" at 39.156,16.998 h1.4 r180
  text "SB5" at 63.141,16.462 h1.91 r180
  text "P1.10" at 79.104,16.462 h1.91 r180
  text "LED 1" at 85.835,16.438 h1.91 r180
  text "P0.00" at 23.819,16.38 h1.91 r180
  text "TXD0" at 30.868,16.369 h1.91 r180
  text "P1.13" at 49.171,15.076 h1.91 r180
  text "XL1" at 56.791,15.054 h1.91 r180
  text "PIN" at 75.231,14.877 h1.78 r180
  text "LED 0" at 85.847,14.572 h1.91 r180
  text "P0.01" at 23.819,13.84 h1.91 r180
  text "RXD0" at 30.856,13.829 h1.91 r180
  text "SB3" at 63.141,13.77 h1.91 r180
  text "P1.24" at 79.104,13.77 h1.91 r180
  text "5.0V" at 97.538,13.344 h1.52 r180
  text "GPIO" at 48.714,11.68 h1.99 r180
  text "Function" at 54.206,11.68 h1.99 r180
  text "Short" at 63.192,11.68 h1.99 r180
  text "GPIO" at 78.681,11.682 h1.99 r180
  text "Function" at 84.152,11.681 h1.99 r180
  text "HW" at 94.63,11.666 h1.99 r180
  text "HW" at 71.777,11.655 h1.99 r180
  text "GPIO" at 23.792,11.289 h2.03 r180
  text "Function" at 29.676,11.286 h2.03 r180
  text "Circuit" at 40.097,11.28 h2.03 r180
Top Solder:
  circle w1.4: c92.825,23.375 r0.25
Board Outline:
  lines w0.05: -2.1,0 1.641,0 ; 0,-2.3 0,2.264
  lines w0.25: 1.016,0 111.604,0 ; 111.571,63.5 112.688,62.383 ccw(c114.9,64.594) 114.9,61.467 ; 111.604,0.004 112.688,1.088 cw(c114.9,-1.123) 114.9,2.004 ; 114.904,2.004 115.709,2.004 ccw(c115.709,3.299) 117.004,3.299 117.004,60.171 ccw(c115.709,60.171) 115.709,61.467 114.904,61.467
  lines w0.254: 1.016,0 cw(c1.016,1.016) 0,1.016 0,62.484 cw(c1.016,62.484) 1.016,63.5 111.571,63.5
Top Impedance Info:
  lines w0.153: 7.489,24.375 cw(c7.727,24.137) 7.727,24.474 10.361,24.474 cw(c10.361,24.165) 10.579,24.383 ; 7.489,24.875 ccw(c7.727,25.113) 7.727,24.777 10.322,24.777 ccw(c10.322,25.141) 10.579,24.883 ; 11.579,24.383 cw(c11.801,24.161) 11.801,24.475 11.879,24.475 13.05,24.475 13.084,24.475 cw(c13.084,22.81) 14.75,22.81 14.75,21.422 ccw(c16.6,21.422) 16.6,19.572 19.033,19.572 cw(c19.033,19.138) 19.467,19.138 19.467,18.664 19.46,18.664 ; 11.579,24.883 ccw(c11.833,25.137) 11.833,24.778 11.879,24.778 13.05,24.778 13.084,24.778 cw(c13.084,22.81) 15.053,22.81 15.053,21.422 ccw(c16.6,21.422) 16.6,19.875 19.033,19.875 cw(c19.033,19.138) 19.77,19.138 19.77,18.755 ccw(c19.86,18.755) 19.86,18.664
  text "90-ohms grounded coplanar differential" at 7.452,25.664 h0.64
Bottom Placement:
  circle w0.15: c19.122,29.997 r0.95
  circle w0.15: c38.919,42.395 r0.95
  circle w0.15: c26.334,48.26 r0.95
  circle w0.15: c15.448,44.856 r0.95
  circle w0.15: c23.621,4.115 r0.95
  circle w0.15: c20.621,4.115 r0.95
  circle w0.15: c26.621,4.115 r0.95
  circle w0.15: c29.621,4.115 r0.95
  circle w0.15: c16.004,2 r0.95
  circle w0.15: c9.135,12.15 r0.95
  circle w0.15: c10.241,23.113 r0.95
  circle w0.15: c10.241,26.115 r0.95
  circle w0.15: c13.263,23.571 r0.95
  circle w0.15: c16.032,27.61 r0.95
  circle w0.15: c21.798,27.432 r0.95
  circle w0.15: c24.798,28.423 r0.95
  circle w0.15: c27.798,28.423 r0.95
  circle w0.15: c37.215,26.746 r0.95
  circle w0.15: c37.215,21.746 r0.95
  circle w0.15: c37.215,16.746 r0.95
  circle w0.15: c37.215,11.746 r0.95
  circle w0.15: c45.496,13.056 r0.95
  circle w0.15: c9.25,31.75 r0.95
  circle w0.15: c10.241,38.353 r0.95
  circle w0.15: c10.241,41.353 r0.95
  circle w0.15: c13.263,38.845 r0.95
  circle w0.15: c32.034,37.567 r0.95
  circle w0.15: c37.419,38.711 r0.95
  circle w0.15: c38.104,47.219 r0.95
  circle w0.15: c36.174,49.2 r0.95
  circle w0.15: c10.698,48.92 r0.95
  circle w0.15: c14.533,54.305 r0.95
  circle w0.15: c18.623,57.582 r0.95
  circle w0.15: c22.077,54.813 r0.95
  circle w0.15: c26.878,54.915 r0.95
  circle w0.15: c23.372,58.039 r0.95
  text "Circles mark PCA10145 v0.9.0 test point locations" at 9.793,61.805 h0.6

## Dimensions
0.029,63.5 to 12.6,58.5 on Dimension
0,0 to 8.004,5 on Dimension
0,63.856 to 12.6,58.5 on Dimension
0,0 to 8,5 on Dimension
8.004,5 to 44.004,5 on Dimension
44.004,58.5 to 113.104,58.5 on Dimension
12.604,58.5 to 44.004,58.5 on Dimension
0,0 to 0,63.5 on Dimension
0,0 to 117.004,0 on Dimension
